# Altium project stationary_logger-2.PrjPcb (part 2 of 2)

## Sheet MCU_Power.SchDoc: Insert Title
size B; DrawnBy: Insert Name; Organization: NH-GG; DocumentNumber: 12345; Revision: 1; SheetNumber: 5; SheetTotal: 11; nhSheetName: MCU Power
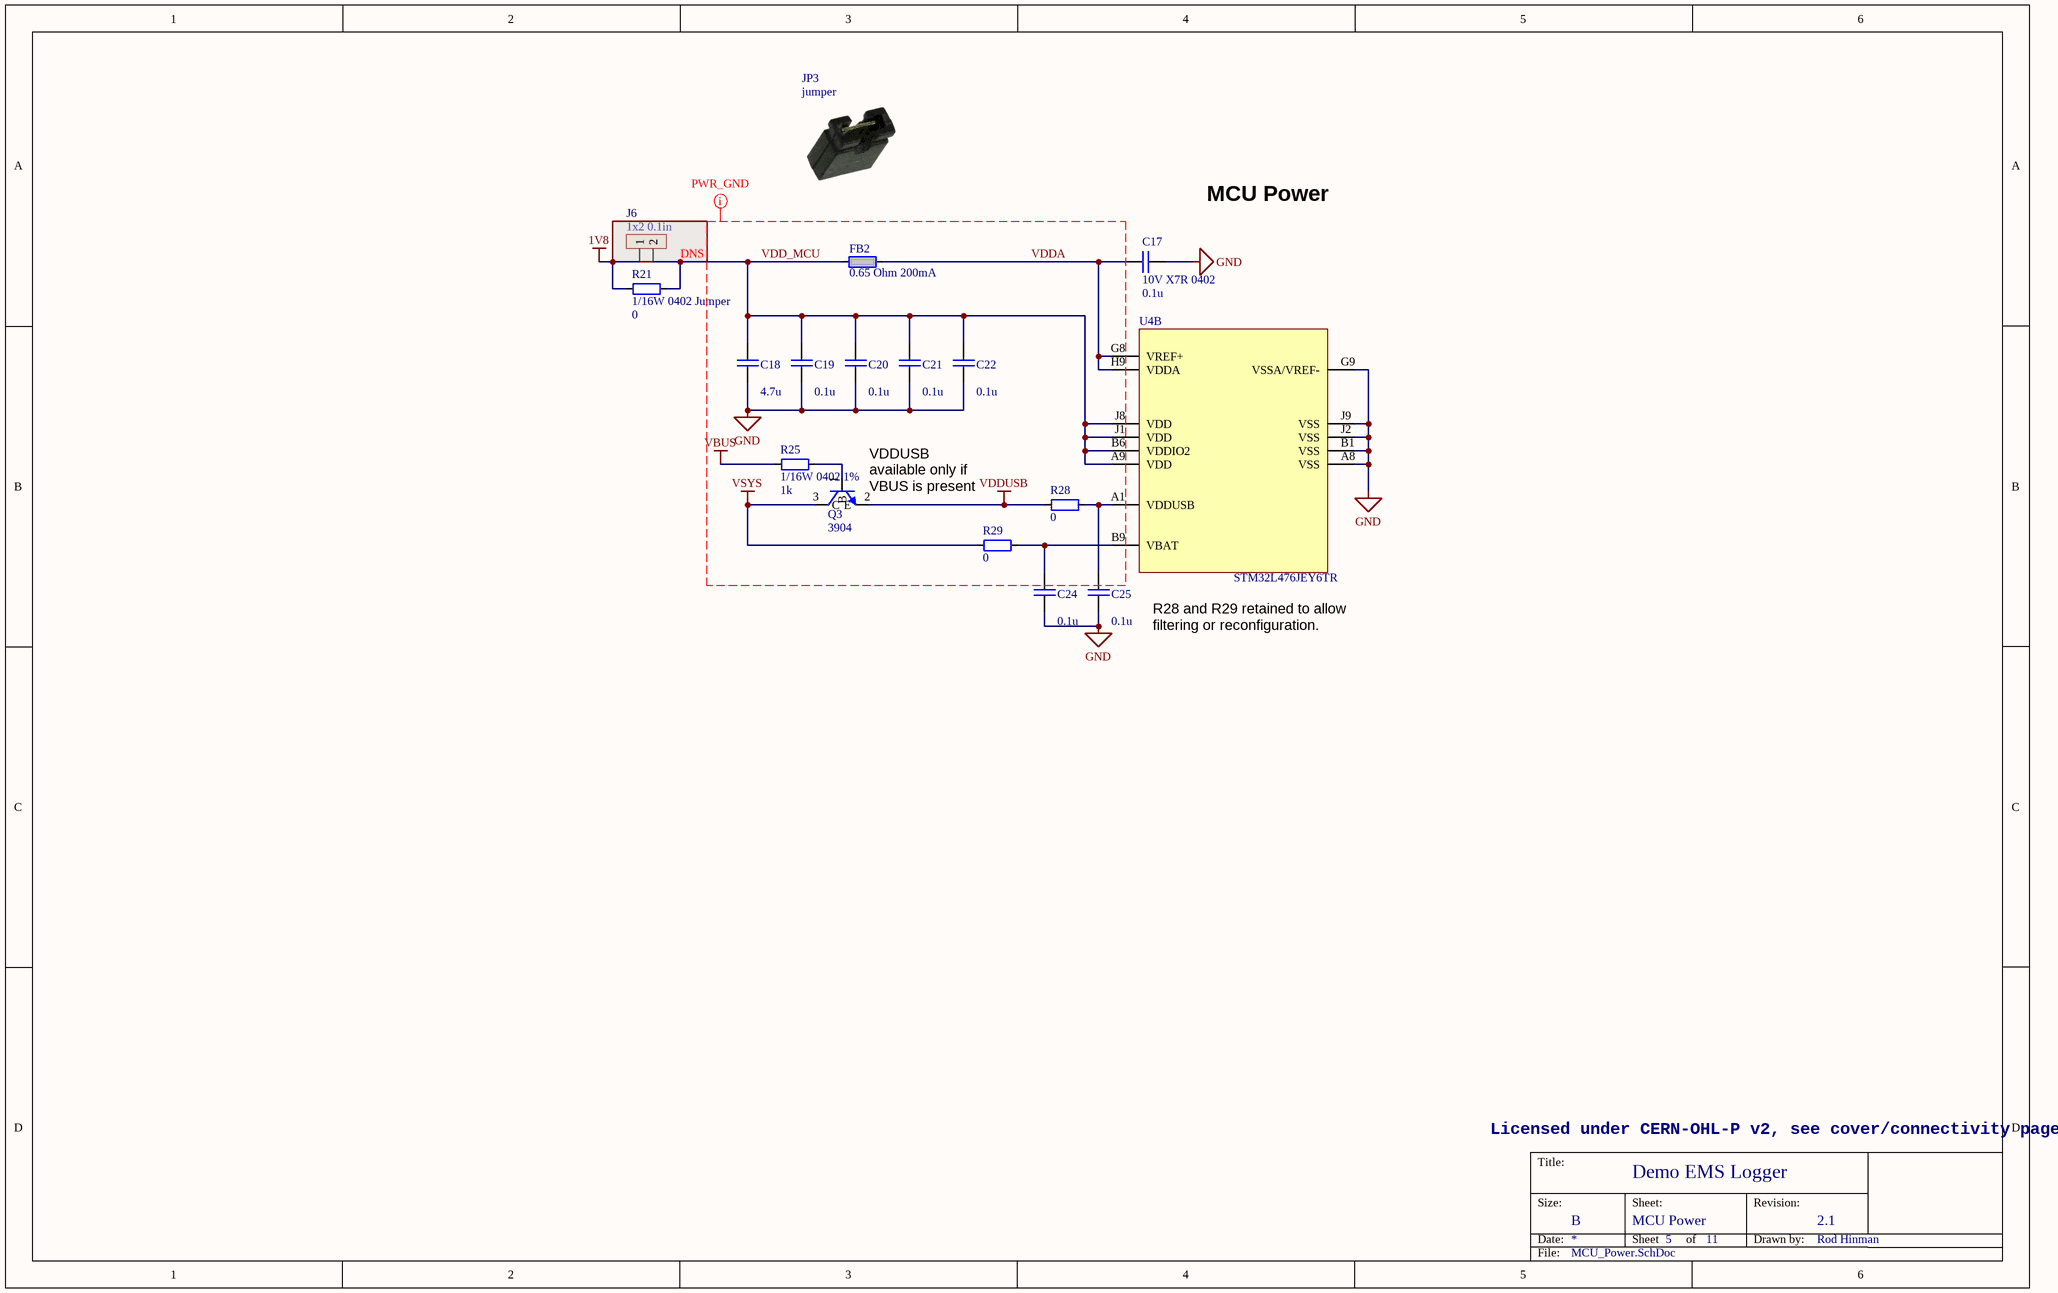
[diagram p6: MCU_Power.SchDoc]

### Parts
C17  10V X7R 0402  value_text: 0.1u  [CAPC1005X55,0402,L]
C18  value_text: 4.7u  [CAPC1608X100,0603,L]  (hidden comment: 16V X7R 0603)
C19  value_text: 0.1u  [CAPC1005X55,0402,L]  (hidden comment: 10V X7R 0402)
C20  value_text: 0.1u  [CAPC1005X55,0402,L]  (hidden comment: 10V X7R 0402)
C21  value_text: 0.1u  [CAPC1005X55,0402,L]  (hidden comment: 10V X7R 0402)
C22  value_text: 0.1u  [CAPC1005X55,0402,L]  (hidden comment: 10V X7R 0402)
C24  value_text: 0.1u  [CAPC1005X55,0402,L]  (hidden comment: 10V X7R 0402)
C25  value_text: 0.1u  [CAPC1005X55,0402,L]  (hidden comment: 10V X7R 0402)
FB2  0.65 Ohm 200mA  [FER1005X60,0402,L]
J6  1x2 0.1in  [HDR_2PIN]
JP3  jumper  [SULLINS_QPC02SXGN-RC]
Q3  3904  [SOT23-3]
R21  1/16W 0402 Jumper  value_text: 0  [RESC1005X40,0402,L]
R25  1/16W 0402 1%  value_text: 1k  [RESC1005X40,0402,L]
R28  value_text: 0  [RESC1005X40,0402,L]  (hidden comment: 1/16W 0402 Jumper)
R29  value_text: 0  [RESC1005X40,0402,L]  (hidden comment: 1/16W 0402 Jumper)
U4  STM32L476JEY6TR  [STM_BGA72C40P9X9_441X376X58]  (part B of 2)

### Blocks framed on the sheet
DNS: J6

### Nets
1V8: J6.1 R21.1
GND: C17.2 C18.1 C19.1 C20.1 C21.1 C22.1 C24.1 C25.1 U4.A8(VSS) U4.B1(VSS) U4.G9(VSSA/VREF-) U4.J2(VSS) U4.J9(VSS)
VBUS: R25.1
VDDUSB: Q3.2(E) R28.2
VSYS: Q3.3(C) R29.2
VDD_MCU: C18.2 C19.2 C20.2 C21.2 C22.2 FB2.1 J6.2 R21.2 U4.A9(VDD) U4.B6(VDDIO2) U4.J1(VDD) U4.J8(VDD)
VDDA: C17.1 FB2.2 U4.G8(VREF+) U4.H9(VDDA)
NetC24_2: C24.2 R29.1 U4.B9(VBAT)
NetC25_2: C25.2 R28.1 U4.A1(VDDUSB)
NetQ3_1: Q3.1(B) R25.2

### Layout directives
net class PWR_GND: GND, VBUS, VDD_MCU, VDDA, VDDUSB, VSYS

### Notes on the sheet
- MCU Power
- (near Q3) VDDUSB available only if VBUS is present
- R28 and R29 retained to allow filtering or reconfiguration.
- Licensed under CERN-OHL-P v2, see cover/connectivity page.

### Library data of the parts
C17 C19-C22 C24 C25 = CAP-00140: 0.1µF ±10% 10V Ceramic Capacitor X7R 0402 (1005 Metric); manufacturer_pn: CL05B104KP5NNNC; manufacturer: Samsung Electro-Mechanics America, Inc.; id: 479140; value: 1E-7
C18 = CAP-00136: CAP CER 4.7UF 16V X5R 0603; manufacturer_pn: CL10A475KO8NNNC; manufacturer: Samsung Electro-Mechanics America, Inc.; id: 468089; value: 4.7E-6
FB2 = FER-00014: FERRITE BEAD 600 OHM 0402 1LN; manufacturer_pn: BLM15BD601SN1D; manufacturer: Murata Electronics North America; id: 468096; value_text: 600; value: 600
J6 = CONN-00001: 2 Positions Header, Unshrouded Connector 0.100" (2.54mm) Through Hole Gold; manufacturer_pn: 961102-6404-AR; manufacturer: 3M; id: 136490
JP3 = MECH-00014: 2 (1 x 2) Position Shunt Connector Black Open Top 0.100" (2.54mm) Gold; manufacturer_pn: QPC02SXGN-RC; manufacturer: Sullins Connector Solutions; id: 138116
Q3 = BJT-00000: TRANS NPN 40V 0.2A SOT23; manufacturer_pn: MMBT3904LT1G; manufacturer: ON Semiconductor; id: 138488
R21 R28 R29 = RES-00093: 0.0 Ohm Jumper 0.063W, 1/16W Chip Resistor 0402 (1005 Metric) Moisture Resistant Thick Film; manufacturer_pn: RC0402JR-070RL; manufacturer: Yageo; id: 168185; value: 0
R25 = RES-00090: 1k Ohm ±1% 0.063W, 1/16W Chip Resistor 0402 (1005 Metric) Moisture Resistant Thick Film; manufacturer_pn: RC0402FR-071KL; manufacturer: Yageo; id: 168133; value: 1000
U4 = MCU-00028: IC MCU 32BIT 512KB FLASH WLCSP72; manufacturer: STMicroelectronics; id: 474854

## Sheet USB.SchDoc: Insert Title
size B; DrawnBy: Insert Name; Organization: NH-GG; DocumentNumber: 12345; Revision: 1; SheetNumber: 9; SheetTotal: 11; nhSheetName: USB
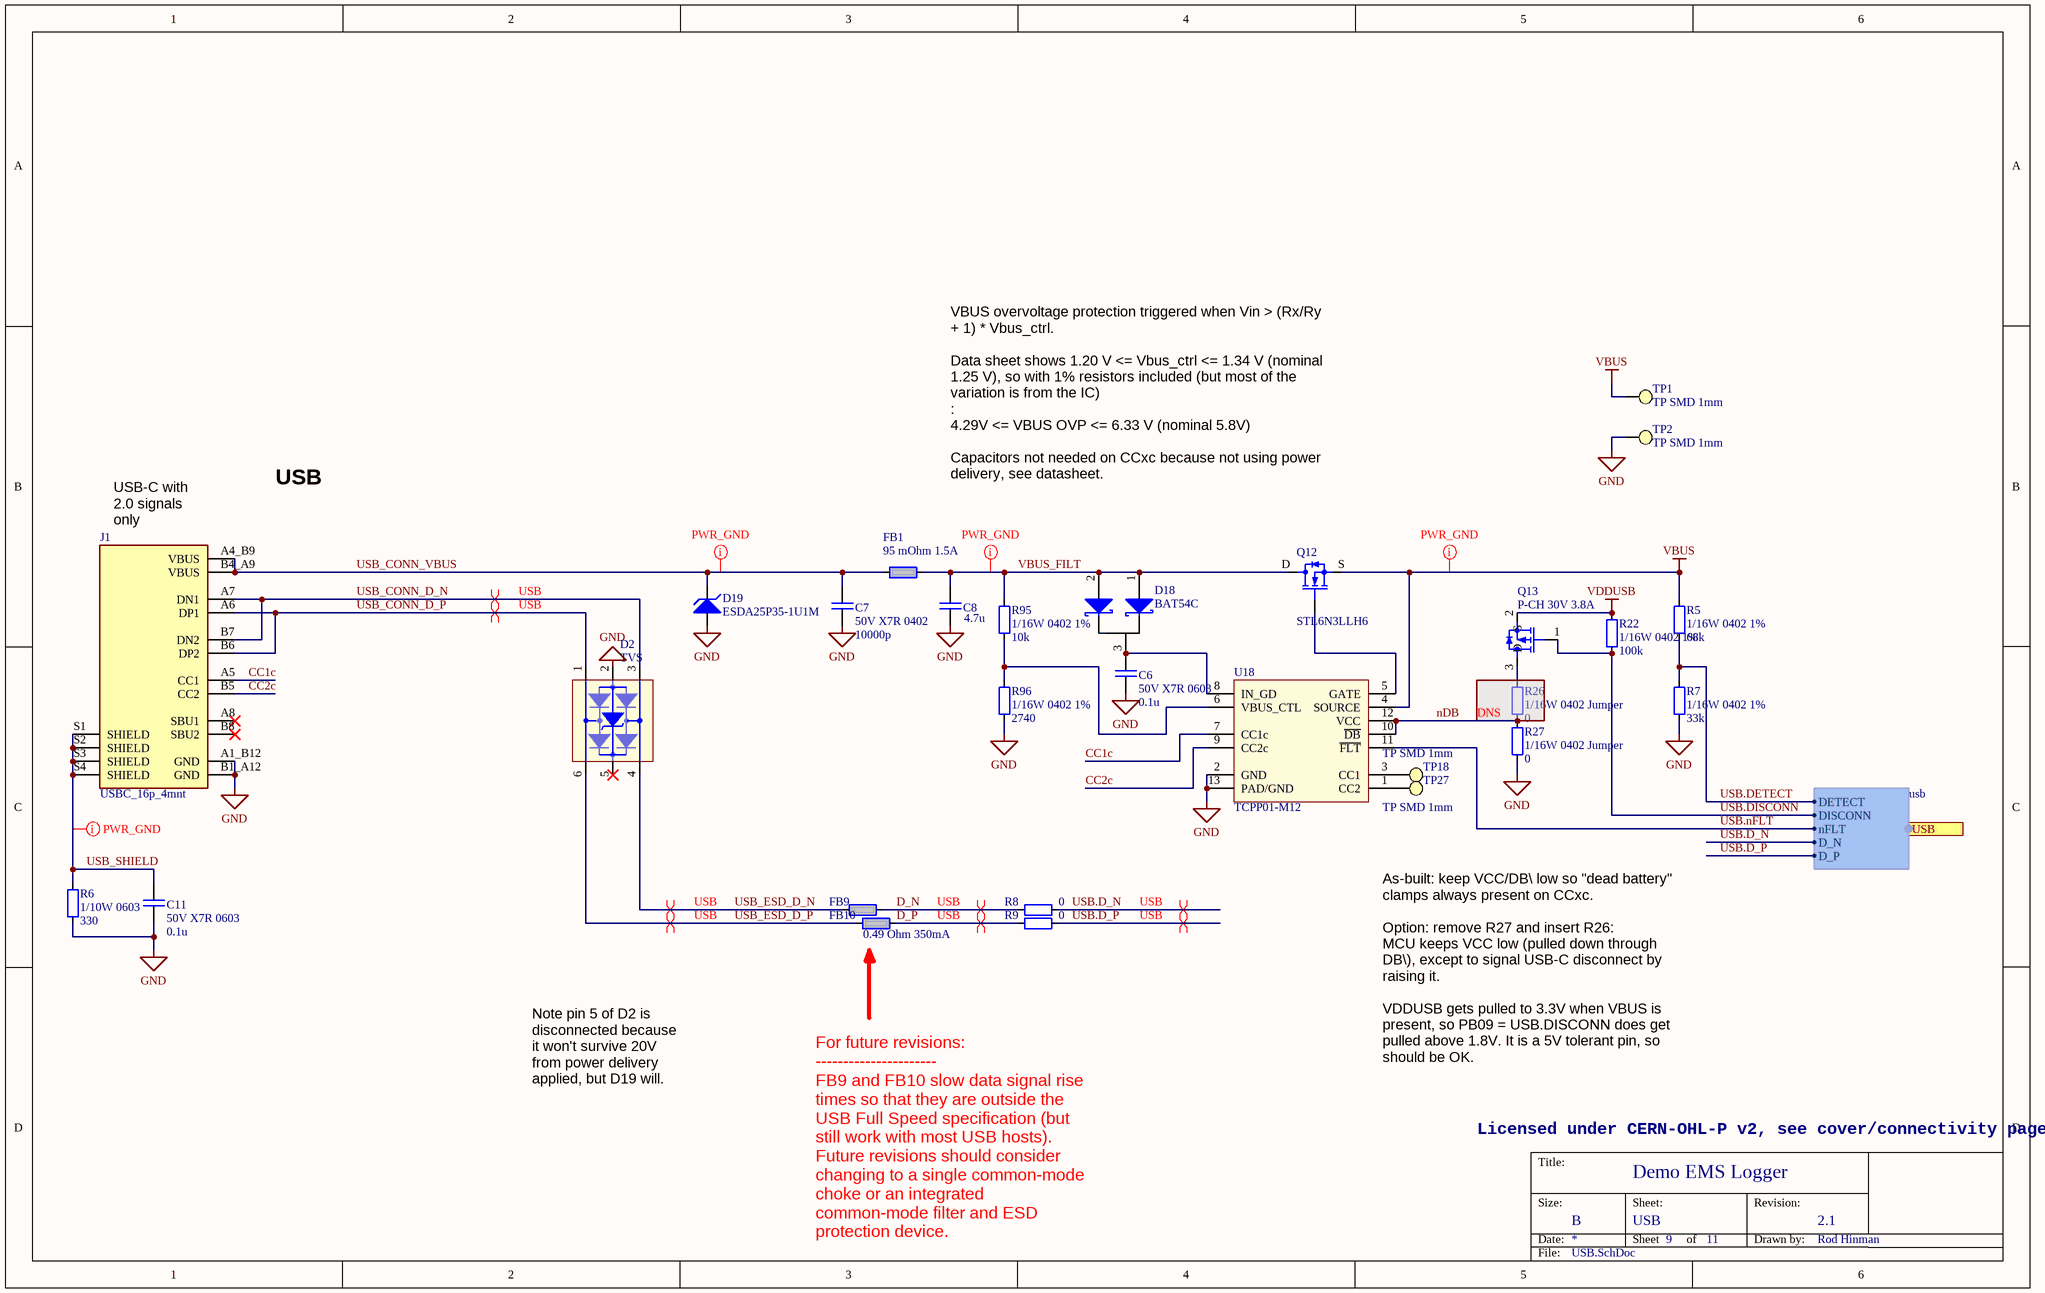
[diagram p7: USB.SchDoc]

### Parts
C6  50V X7R 0603  value_text: 0.1u  [CAPC1608X100,0603,L]
C7  50V X7R 0402  value_text: 10000p  [CAPC1005X60,0402,L]
C8  value_text: 4.7u  [CAPC1608X100,0603,L]  (hidden comment: 16V X7R 0603)
C11  50V X7R 0603  value_text: 0.1u  [CAPC1608X100,0603,L]
D2  TVS  [SOT23-6]
D18  BAT54C  [SOT23-3B]
D19  manufacturer_pn: ESDA25P35-1U1M  [DFN105P160X60-2N]  (hidden comment: 22WVM)
FB1  95 mOhm 1.5A  [FER1005X60,0402,L]
FB9  0.49 Ohm 350mA  [FER1005X60,0402,L]  (value not drawn)
FB10  0.49 Ohm 350mA  [FER1005X60,0402,L]
J1  USBC_16p_4mnt  [GCT_USB4105]
Q12  manufacturer_pn: STL6N3LLH6  [STM_PWRFLAT_SON65P200X80_HS-8N]  (hidden comment: N-CH 30V)
Q13  P-CH 30V 3.8A  [SOT23-3]
R5  1/16W 0402 1%  value_text: 68k  [RESC1005X40,0402,L]
R6  1/10W 0603  value_text: 330  [RESC1608X60,0603,L]
R7  1/16W 0402 1%  value_text: 33k  [RESC1005X40,0402,L]
R8  value_text: 0  [RESC1005X40,0402,L]  (hidden comment: 1/16W 0402 Jumper)
R9  value_text: 0  [RESC1005X40,0402,L]  (hidden comment: 1/16W 0402 Jumper)
R22  1/16W 0402 1%  value_text: 100k  [RESC1005X40,0402,L]
R26  1/16W 0402 Jumper  value_text: 0  [RESC1005X40,0402,L]
R27  1/16W 0402 Jumper  value_text: 0  [RESC1005X40,0402,L]
R95  1/16W 0402 1%  value_text: 10k  [RESC1005X40,0402,L]
R96  1/16W 0402 1%  value_text: 2740  [RESC1005X40,0402,L]
TP1  TP SMD 1mm  [TP_SMD_Ø1.0mm NO SILK]  (no BOM)
TP2  TP SMD 1mm  [TP_SMD_Ø1.0mm NO SILK]  (no BOM)
TP18  TP SMD 1mm  [TP_SMD_Ø1.0mm NO SILK]  (no BOM)
TP27  TP SMD 1mm  [TP_SMD_Ø1.0mm NO SILK]  (no BOM)
U18  manufacturer_pn: TCPP01-M12  [QFN50P300X300X100_HS-13N]  (hidden comment: STM_TCPP01-M12)

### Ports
USB (out, harness usb)

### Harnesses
usb: DETECT, DISCONN, D_N, D_P, nFLT

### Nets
GND: C6.2 C7.1 C8.1 C11.2 D2.2(GND) D19.A J1.A1_B12(GND) J1.B1_A12(GND) R6.2 R7.1 R27.1 R96.1 TP2.1 U18.2(GND) U18.13(PAD/GND)
VBUS: Q12.S R5.2 TP1.1 U18.4(SOURCE)
VDDUSB: Q13.2(S) R22.1
CC1c: J1.A5(CC1) U18.7(CC1c)
CC2c: J1.B5(CC2) U18.9(CC2c)
D_N: FB9.2 R8.2
D_P: FB10.2 R9.2
nDB: R26.1 R27.2 U18.10(~{DB}) U18.12(VCC)
USB.D_N: R8.1 ; port USB.D_N
USB.D_P: R9.1 ; port USB.D_P
USB.DETECT: R5.1 R7.2 ; port USB.DETECT
USB.DISCONN: Q13.1(G) R22.2 ; port USB.DISCONN
USB.nFLT: U18.11(~{FLT}) ; port USB.nFLT
USB_CONN_D_N: D2.3(D-IN) J1.A7(DN1) J1.B7(DN2)
USB_CONN_D_P: D2.1(D+IN) J1.A6(DP1) J1.B6(DP2)
USB_CONN_VBUS: C7.2 D19.K FB1.1 J1.A4_B9(VBUS) J1.B4_A9(VBUS)
USB_ESD_D_N: D2.4(D-OUT) FB9.1
USB_ESD_D_P: D2.6(D+OUT) FB10.1
USB_SHIELD: C11.1 J1.S1(SHIELD) J1.S2(SHIELD) J1.S3(SHIELD) J1.S4(SHIELD) R6.1
VBUS_FILT: C8.2 D18.1 D18.2 FB1.2 Q12.D R95.2
NetC6_1: C6.1 D18.3 U18.8(IN_GD)
NetQ12_G: Q12.G U18.5(GATE)
NetQ13_3: Q13.3(D) R26.2
NetR95_1: R95.1 R96.2 U18.6(VBUS_CTL)
NetTP18_1: TP18.1 U18.3(CC1)
NetTP27_1: TP27.1 U18.1(CC2)

Not connected (* = marked no-connect by the designer): D2 5(VBUS)*; J1 A8(SBU1)* B8(SBU2)*

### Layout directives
net class PWR_GND: USB_CONN_VBUS, USB_SHIELD, VBUS, VBUS_FILT
differential pair; differential pair class USB; net class USB: D_N, D_P, USB.D_N, USB.D_P, USB_CONN_D_N, USB_CONN_D_P, USB_ESD_D_N, USB_ESD_D_P

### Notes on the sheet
- USB
- VBUS overvoltage protection triggered when Vin > (Rx/Ry + 1) * Vbus_ctrl.
  Data sheet shows 1.20 V <= Vbus_ctrl <= 1.34 V (nominal 1.25 V), so with 1% resistors included (but most of the variation is from the IC)
  :
  4.29V <= VBUS OVP <= 6.33 V (nominal 5.8V)
  Capacitors not needed on CCxc because not using power delivery, see datasheet.
- (near J1) USB-C with 2.0 signals only
- DNS
- As-built: keep VCC/DB\ low so "dead battery" clamps always present on CCxc.
  Option: remove R27 and insert R26:
  MCU keeps VCC low (pulled down through DB\), except to signal USB-C disconnect by raising it.
  VDDUSB gets pulled to 3.3V when VBUS is present, so PB09 = USB.DISCONN does get pulled above 1.8V. It is a 5V tolerant pin, so should be OK.
- Note pin 5 of D2 is disconnected because it won't survive 20V from power delivery applied, but D19 will.
- Licensed under CERN-OHL-P v2, see cover/connectivity page.
- For future revisions:
  ----------------------
  FB9 and FB10 slow data signal rise times so that they are outside the USB Full Speed specification (but still work with most USB hosts).  Future revisions should consider changing to a single common-mode choke or an integrated common-mode filter and ESD protection device.

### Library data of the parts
C6 C11 = CAP-00138: CAP CER 0.1UF 50V X7R 0603; manufacturer_pn: CL10B104KB8NNNC; manufacturer: Samsung Electro-Mechanics America, Inc.; id: 468091; value: 1E-7
C7 = CAP-00114: 10000pF ±10% 50V Ceramic Capacitor X7R 0402 (1005 Metric); manufacturer_pn: C0402C103K5RAC7867; manufacturer: Kemet; id: 288967; value: 1E-8
C8 = CAP-00136: as C18 on sheet MCU_Power
D2 = DIO-00054: TVS DIODE 5.25VWM 17VC SOT23-6; manufacturer_pn: USBLC6-2SC6; manufacturer: STMicroelectronics; id: 468100
D18 = DIO-00052: Diode Array 1 Pair Common Cathode Schottky 30 V 200mA (DC) Surface Mount TO-236-3, SC-59, SOT-23-3; manufacturer_pn: BAT54C,215; manufacturer: Nexperia USA Inc.; id: 460427
D19 = DIO-00057: TVS DIODE 22VWM 31VC; manufacturer: STMicroelectronics; id: 475009
FB1 = FER-00015: FERRITE BEAD 220 OHM 0402 1LN; manufacturer_pn: MPZ1005S221HT000; manufacturer: TDK Corporation; id: 468097; value_text: 220; value: 220
FB9 FB10 = FER-00013: FERRITE BEAD 1 KOHM 0402 1LN; manufacturer_pn: BLM15AX102SN1D; manufacturer: Murata Electronics North America; id: 468095; value_text: 1k; value: 1000
J1 = CONN-00185: CONN RCP USB2.0 TYP C 24P SMD RA; manufacturer: GCT; manufacturer_pn: USB4105-GF-A; id: 477100; MF: CUI Devices; MP: UJ31-CH-3-MSMT-TR-67
Q12 = FET-00031: MOSFET N-Ch 30 V 0.021 Ohm 6 A; manufacturer: STMicroelectronics; id: 475008
Q13 = FET-00028: MOSFET P-CH 30V 3.8A SOT23; manufacturer_pn: DMP3099L-7; manufacturer: Diodes Incorporated; id: 468113
R5 = RES-00197: RES 68K OHM 1% 1/16W 0402; manufacturer_pn: RC0402FR-0768KL; manufacturer: Yageo; id: 468078; value: 68000
R6 = RES-00202: RES SMD 330 OHM 1% 1/10W 0603; manufacturer_pn: ERJ-3EKF3300V; manufacturer: Panasonic Electronic Components; id: 468084; value: 330
R7 = RES-00198: RES 33K OHM 1% 1/16W 0402; manufacturer_pn: RC0402FR-0733KL; manufacturer: Yageo; id: 468079; value: 33000
R8 R9 R26 R27 = RES-00093: as R21 on sheet MCU_Power
R22 = RES-00095: 100k Ohm ±1% 0.063W, 1/16W Chip Resistor 0402 (1005 Metric) Moisture Resistant Thick Film; manufacturer_pn: RC0402FR-07100KL; manufacturer: Yageo; id: 168197; value: 100000
R95 = RES-00094: 10k Ohm ±1% 0.063W, 1/16W Chip Resistor 0402 (1005 Metric) Moisture Resistant Thick Film; manufacturer_pn: RC0402FR-0710KL; manufacturer: Yageo; id: 168195; value: 10000
R96 = RES-00205: RES 2.74K OHM 1% 1/16W 0402; manufacturer_pn: RC0402FR-072K74L; manufacturer: Yageo; id: 475656; value: 2740
TP1 TP2 TP18 TP27 = NOBOM-00001: Test point, SMD, 1mm dia (0.040"); manufacturer: New Horizons; id: 137197
U18 = ICXCV-00034: USB-C interface IC Overvoltage Protection; manufacturer: STMicroelectronics; id: 474978

## Sheet XX-Changelog.SchDoc: Insert Title
size B; DrawnBy: Insert Name; Organization: NH-GG; DocumentNumber: 12345; Revision: 1; SheetNumber: 11; SheetTotal: 11; nhSheetName: Change Log
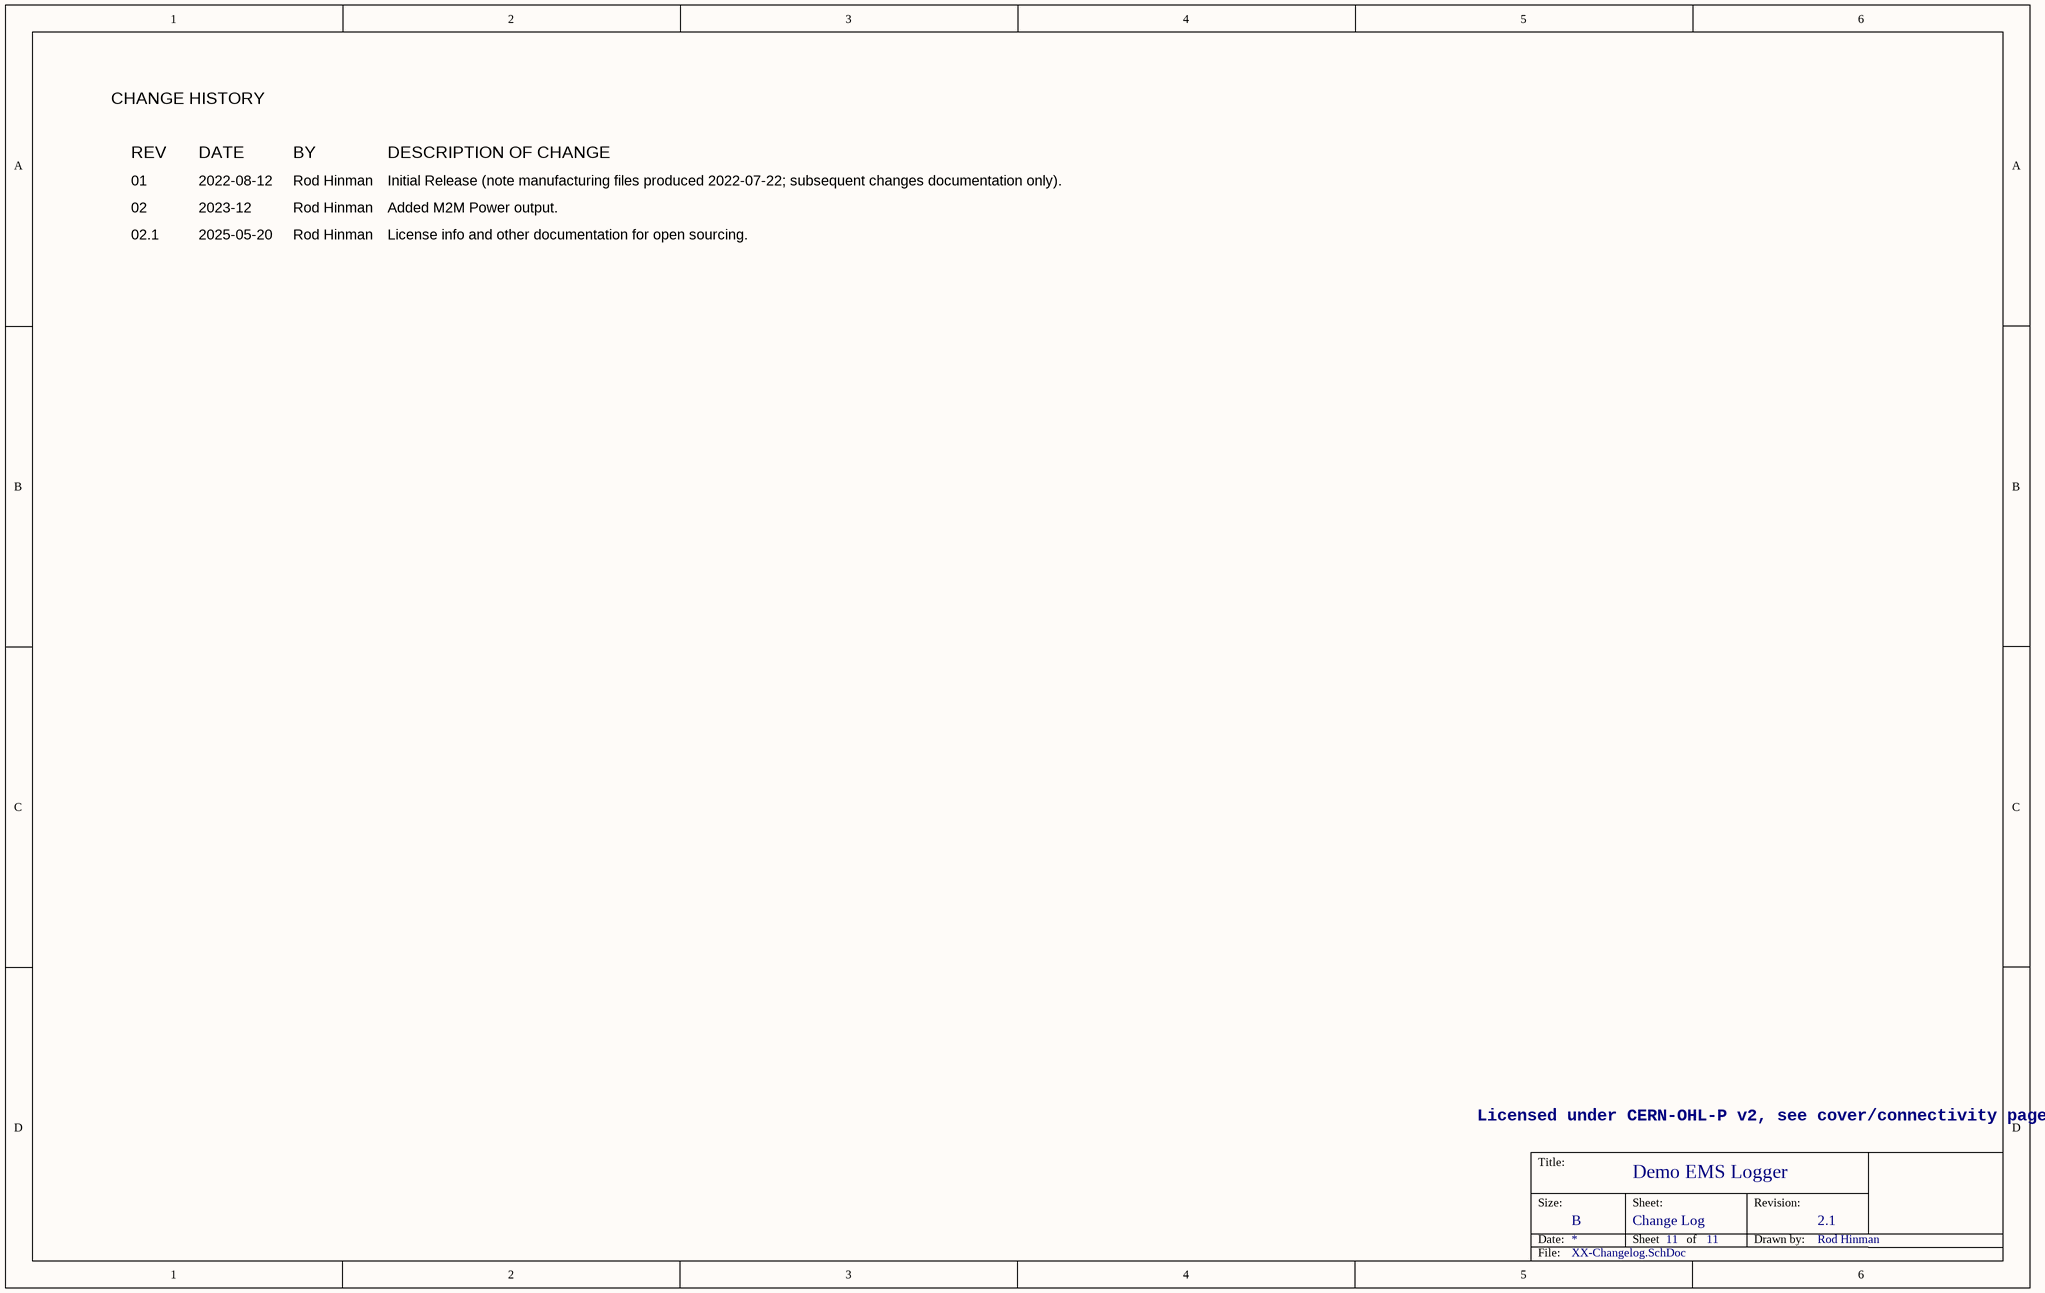
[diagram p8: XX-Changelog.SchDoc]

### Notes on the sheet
- CHANGE HISTORY
- REV
- DATE
- BY
- DESCRIPTION OF CHANGE
- 01
- 02
- 2022-08-12
- 2023-12
- Rod Hinman
- Initial Release (note manufacturing files produced 2022-07-22; subsequent changes documentation only).
- Added M2M Power output.
- 02.1
- 2025-05-20
- License info and other documentation for open sourcing.
- Licensed under CERN-OHL-P v2, see cover/connectivity page.

## Sheet Overview.SchDoc
size B; DrawnBy: Insert Name; Organization: NH-GG; DocumentNumber: 12345; Revision: 1; SheetNumber: 2; SheetTotal: 11; nhSheetName: Overview / General Info
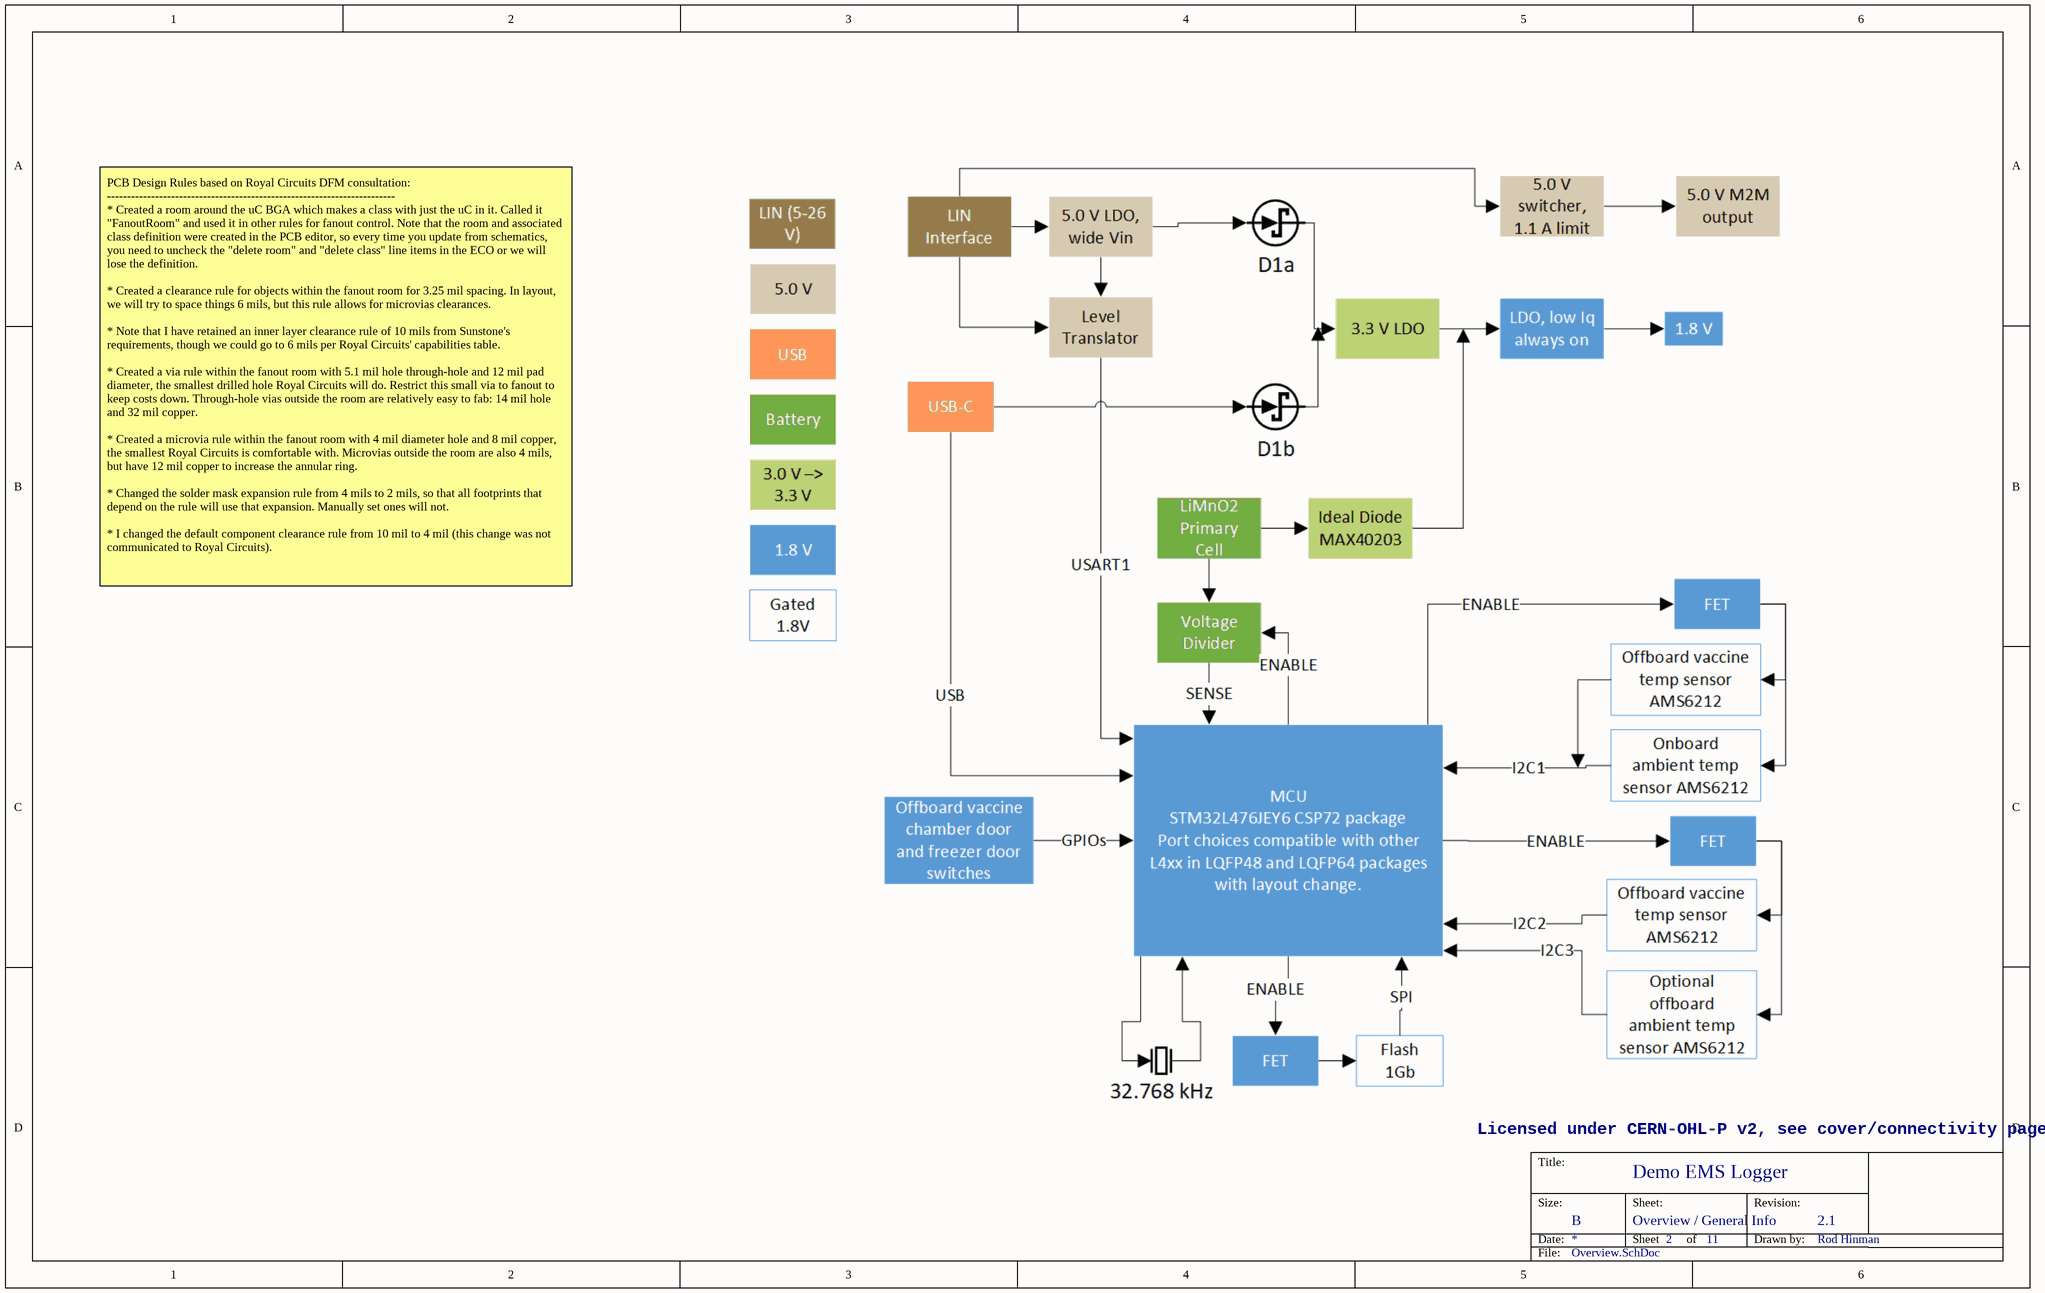
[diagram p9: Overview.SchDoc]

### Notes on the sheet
- PCB Design Rules based on Royal Circuits DFM consultation:
  ------------------------------------------------------------------------
  * Created a room around the uC BGA which makes a class with just the uC in it. Called it "FanoutRoom" and used it in other rules for fanout control. Note that the room and associated class definition were created in the PCB editor, so every time you update from schematics, you need to uncheck the "delete room" and "delete class" line items in the ECO or we will lose the definition.
  * Created a clearance rule for objects within the fanout room for 3.25 mil spacing. In layout, we will try to space things 6 mils, but this rule allows for microvias clearances.
  * Note that I have retained an inner layer clearance rule of 10 mils from Sunstone's requirements, though we could go to 6 mils per Royal Circuits' capabilities table.
  * Created a via rule within the fanout room with 5.1 mil hole through-hole and 12 mil pad diameter, the smallest drilled hole Royal Circuits will do. Restrict this small via to fanout to keep costs down. Through-hole vias outside the room are relatively easy to fab: 14 mil hole and 32 mil copper.
  * Created a microvia rule within the fanout room with 4 mil diameter hole and 8 mil copper, the smallest Royal Circuits is comfortable with. Microvias outside the room are also 4 mils, but have 12 mil copper to increase the annular ring.
  * Changed the solder mask expansion rule from 4 mils to 2 mils, so that all footprints that depend on the rule will use that expansion. Manually set ones will not.
  * I changed the default component clearance rule from 10 mil to 4 mil (this change was not communicated to Royal Circuits).
- Licensed under CERN-OHL-P v2, see cover/connectivity page.

## Sheet M2M_Power.SchDoc: Insert Title
size B; DrawnBy: Insert Name; Organization: NH-GG; DocumentNumber: 12345; Revision: 1; SheetNumber: 10; SheetTotal: 11; nhSheetName: M2M Power
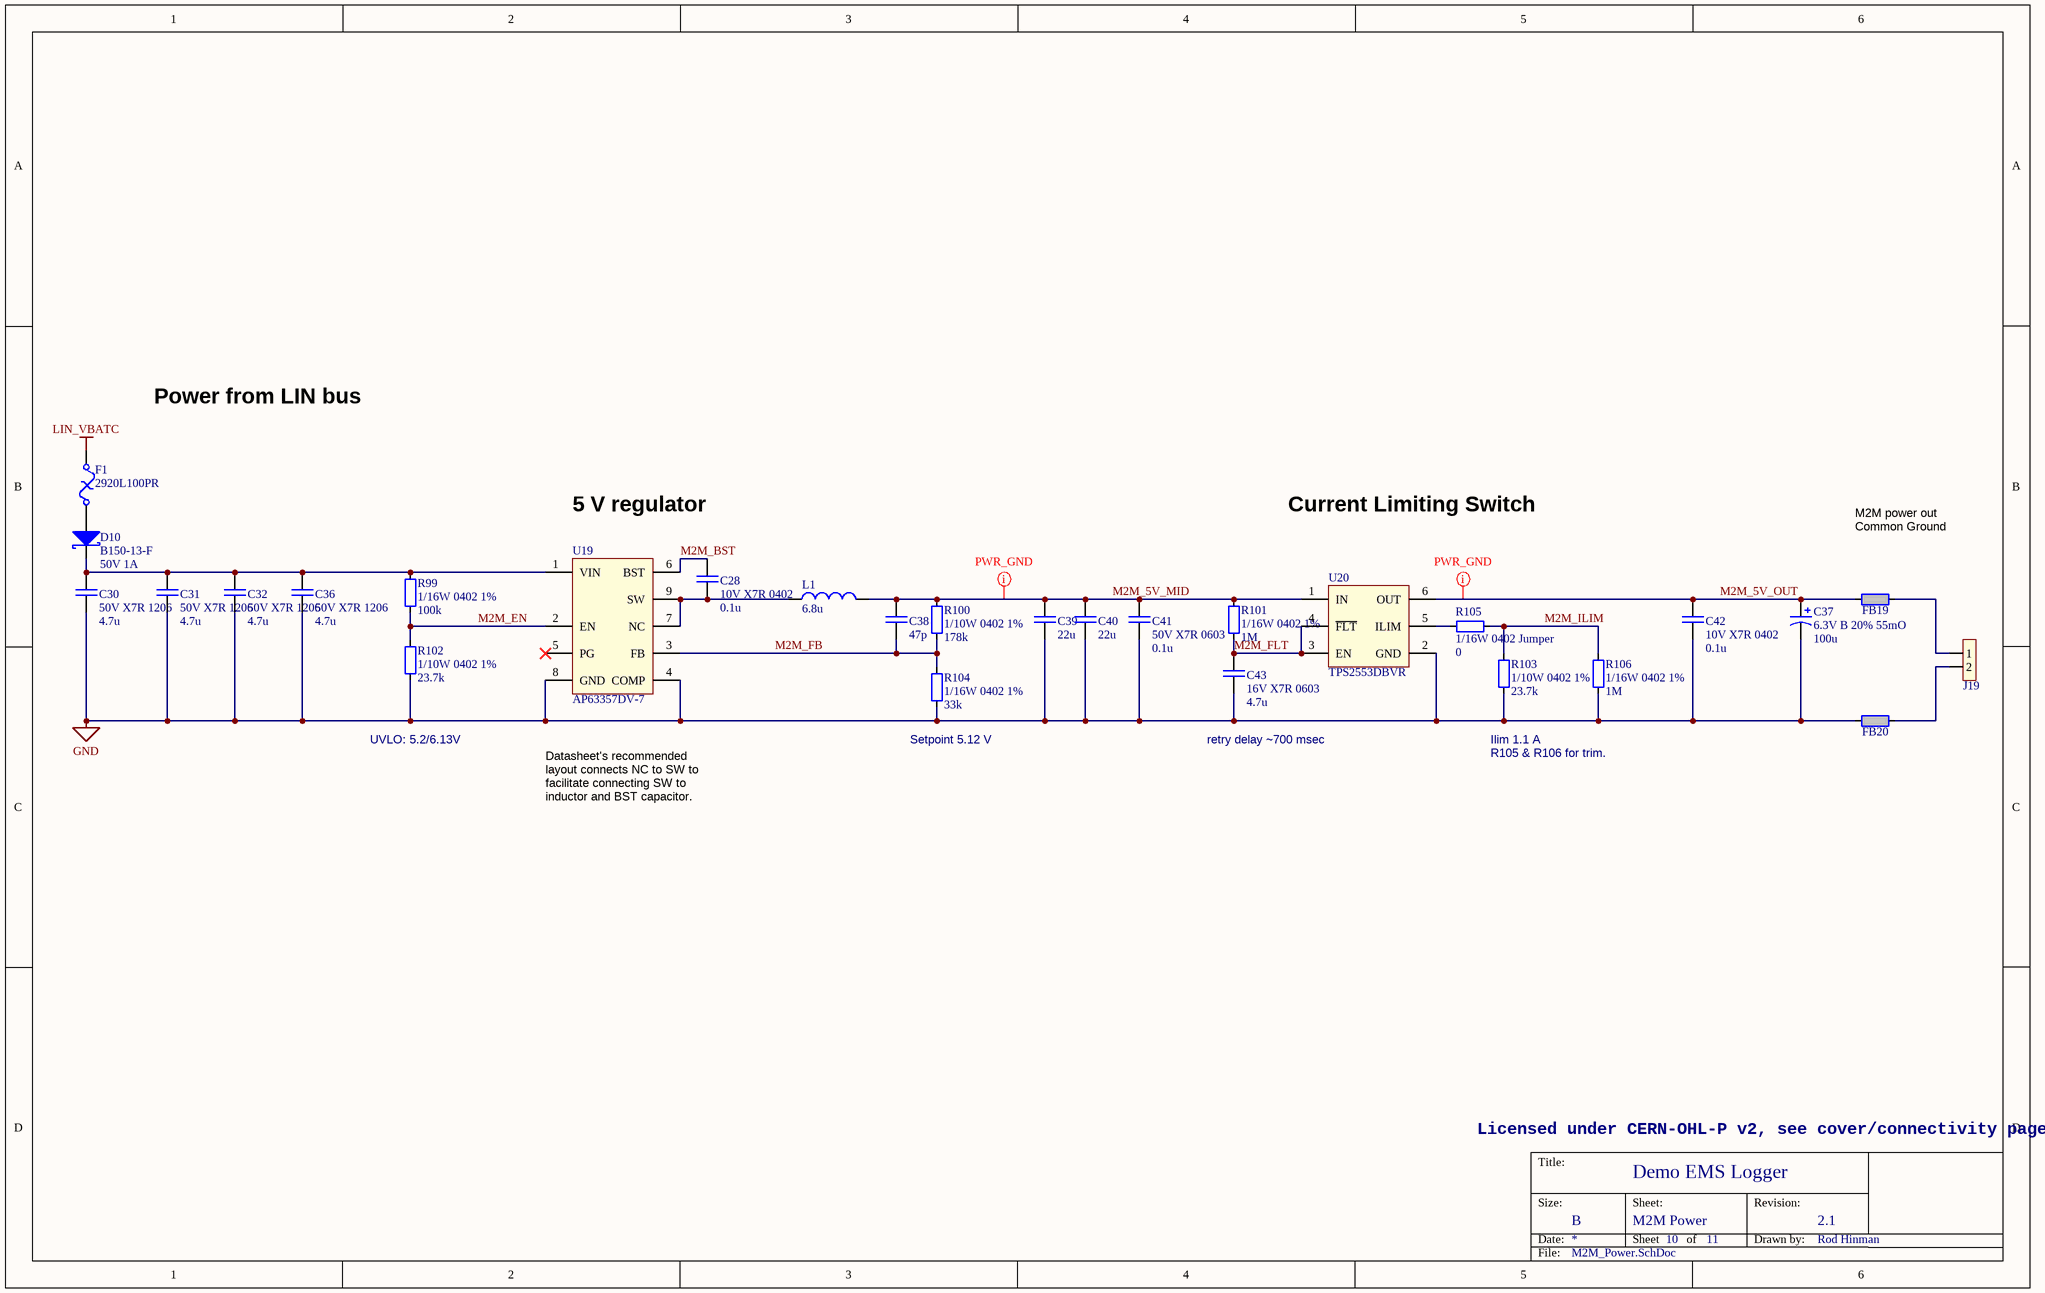
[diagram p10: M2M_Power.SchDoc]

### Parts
C28  10V X7R 0402  value_text: 0.1u  [CAPC1005X55,0402,L]
C30  50V X7R 1206  value_text: 4.7u  [CAPC3216X190,1206,L]
C31  50V X7R 1206  value_text: 4.7u  [CAPC3216X190,1206,L]
C32  50V X7R 1206  value_text: 4.7u  [CAPC3216X190,1206,L]
C36  50V X7R 1206  value_text: 4.7u  [CAPC3216X190,1206,L]
C37  6.3V B 20% 55mO  value_text: 100u  [CAPMP3528X21N[SIZEB]]
C38  value_text: 47p  [CAPC1005X55,0402,L]  (hidden comment: 50V C0G 0402)
C39  value_text: 22u  [CAPC2012X145]  (hidden comment: 16V X5R 0805)
C40  value_text: 22u  [CAPC2012X145]  (hidden comment: 16V X5R 0805)
C41  50V X7R 0603  value_text: 0.1u  [CAPC1608X100,0603,L]
C42  10V X7R 0402  value_text: 0.1u  [CAPC1005X55,0402,L]
C43  16V X7R 0603  value_text: 4.7u  [CAPC1608X100,0603,L]
D10  50V 1A  manufacturer_pn: B150-13-F  [DO-214AC_DIODES]
F1  manufacturer_pn: 2920L100PR  [FUSC7351X12N,2920,]  (hidden comment: 33V 1.1A)
FB19  220 Ohm 2A  [FER1608X100,0603,L]  (value not drawn)
FB20  220 Ohm 2A  [FER1608X100,0603,L]  (value not drawn)
J19  JST XH  [JST_S2B-XH-A(LF)(SN)_LESS_SILK]  (value not drawn)
L1  value_text: 6.8u  [INDUCTOR-BOURNS_SRN6045]  (hidden comment: 3A 31mOhm)
R99  1/16W 0402 1%  value_text: 100k  [RESC1005X40,0402,L]
R100  1/10W 0402 1%  value_text: 178k  [RESC1005X40,0402,L]
R101  1/16W 0402 1%  value_text: 1M  [RESC1005X40,0402,L]
R102  1/10W 0402 1%  value_text: 23.7k  [RESC1005X40,0402,L]
R103  1/10W 0402 1%  value_text: 23.7k  [RESC1005X40,0402,L]
R104  1/16W 0402 1%  value_text: 33k  [RESC1005X40,0402,L]
R105  1/16W 0402 Jumper  value_text: 0  [RESC1005X40,0402,L]
R106  1/16W 0402 1%  value_text: 1M  [RESC1005X40,0402,L]
U19  manufacturer_pn: AP63357DV-7  [DIO_VDFN3020-13A]  (hidden comment: DIO-AP6335x)
U20  manufacturer_pn: TPS2553DBVR  [SOT_23_6]  (hidden comment: TI_TPS2553)

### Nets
GND: C30.1 C31.1 C32.1 C36.1 C37.- C39.2 C40.2 C41.1 C42.1 C43.1 FB20.1 R102.2 R103.2 R104.2 R106.2 U19.4(COMP) U19.8(GND) U20.2(GND)
LIN_VBATC: F1.2
M2M_5V_MID: C38.1 C39.1 C40.1 C41.2 L1.2 R100.1 R101.1 U20.1(IN)
M2M_5V_OUT: C37.+ C42.2 FB19.1 U20.6(OUT)
M2M_BST: C28.2 U19.6(BST)
M2M_EN: R99.2 R102.1 U19.2(EN)
M2M_FB: C38.2 R100.2 R104.1 U19.3(FB)
M2M_FLT: C43.2 R101.2 U20.3(EN) U20.4(~{FLT})
M2M_ILIM: R103.1 R105.2 R106.1
NetC28_1: C28.1 L1.1 U19.7(NC) U19.9(SW)
NetC30_2: C30.2 C31.2 C32.2 C36.2 D10.K R99.1 U19.1(VIN)
NetD10_A: D10.A F1.1
NetFB19_2: FB19.2 J19.1
NetFB20_2: FB20.2 J19.2
NetR105_1: R105.1 U20.5(ILIM)

Not connected (* = marked no-connect by the designer): U19 5(PG)*

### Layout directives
net class PWR_GND: M2M_5V_MID, M2M_5V_OUT

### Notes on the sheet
- Power from LIN bus
- 5 V regulator
- Current Limiting Switch
- (near FB19) M2M power out
  Common Ground
- UVLO: 5.2/6.13V
- (near R104) Setpoint 5.12 V
- retry delay ~700 msec
- Ilim 1.1 A
- R105 & R106 for trim.
- Datasheet's recommended layout connects NC to SW to facilitate connecting SW to inductor and BST capacitor.
- Licensed under CERN-OHL-P v2, see cover/connectivity page.

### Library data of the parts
C28 C42 = CAP-00140: as C17 on sheet MCU_Power
C30-C32 C36 = CAP-00142: 4.7 µF ±10% 50V Ceramic Capacitor X7R 1206 (3216 Metric); manufacturer_pn: C1206C475K5RAC7800; manufacturer: Kemet; id: 486592; value: 4.7E-6; reorder_quantity: 0
C37 = CAP-00029: 100µF Molded Tantalum - Polymer Capacitors 6.3V 1210 (3528 Metric) 55 mOhm 0.138" L x 0.110" W (3.50mm x 2.80mm); manufacturer_pn: TCJB107M006R0055; manufacturer: AVX Corporation; id: 137128; value: 0.0001; reorder_quantity: 0
C38 = CAP-00104: 47pF ±5% 50V Ceramic Capacitor C0G, NP0 0402 (1005 Metric); manufacturer: Wurth Electronics Inc; manufacturer_pn: 885012005059; id: 226042; reorder_quantity: 0; value: 4.7E-11
C39 C40 = CAP-00031: 22µF 16V Ceramic Capacitor X5R 0805 (2012 Metric) 0.079" L x 0.049" W (2.00mm x 1.25mm); manufacturer: Murata Electronics North America; manufacturer_pn: GRM21BR61C226ME44L; id: 137130; reorder_quantity: 0; value: 2.2E-5
C41 = CAP-00138: CAP CER 0.1UF 50V X7R 0603; manufacturer_pn: CL10B104KB8NNNC; manufacturer: Samsung Electro-Mechanics America, Inc.; id: 468091; value: 1E-7; reorder_quantity: 0
C43 = CAP-00136: CAP CER 4.7UF 16V X5R 0603; manufacturer_pn: CL10A475KO8NNNC; manufacturer: Samsung Electro-Mechanics America, Inc.; id: 468089; value: 4.7E-6; reorder_quantity: 0
D10 = DIO-00063: DIODE SCHOTTKY 50V 1A SMA; manufacturer: Diodes Incorporated; id: 520214; reorder_quantity: 0
F1 = FUSE-00012: Polymeric PTC Resettable Fuse 33V 1.1A Ih Surface Mount 2920 (7351 Metric), Concave; manufacturer: Littelfuse Inc.; id: 225978; reorder_quantity: 0
FB19 FB20 = FER-00004: FERRITE BEAD 220 OHM 0603 1LN 50m ohm; manufacturer_pn: BLM18EG221SN1D; manufacturer: Murata Electronics North America; value_text: 220; id: 137076; reorder_quantity: 0; value: 220
J19 = CONN-00192: CONN HEADER R/A 2POS 2.5MM; manufacturer_pn: S2B-XH-A(LF)(SN); manufacturer: JST Sales America Inc.; id: 516837; reorder_quantity: 0
L1 = IND-00035: FIXED IND 6.8UH 3A 31 MOHM SMD; manufacturer_pn: TYS60456R8M-10; manufacturer: Laird Technologies EMI; id: 516835; reorder_quantity: 0; value: 6.8E-6
R99 = RES-00095: as R22 on sheet USB
R100 = RES-00214: RES 178K OHM 1% 1/16W 0402; manufacturer_pn: RC0402FR-07178KL; manufacturer: Yageo; id: 516838; value: 178000; reorder_quantity: 0
R101 R106 = RES-00137: 1 MOhms ±1% 0.063W, 1/16W Chip Resistor 0402 (1005 Metric) Automotive AEC-Q200 Thick Film; manufacturer_pn: RC0402FR-071ML; manufacturer: Vishay Dale; id: 225970; value: 1000000; reorder_quantity: 0
R102 R103 = RES-00213: RES 23.7K OHM 1% 1/16W 0402; manufacturer_pn: RC0402FR-0723K7L; manufacturer: Yageo; id: 516836; value: 23700; reorder_quantity: 0
R104 = RES-00198: RES 33K OHM 1% 1/16W 0402; manufacturer_pn: RC0402FR-0733KL; manufacturer: Yageo; id: 468079; value: 33000; reorder_quantity: 0
R105 = RES-00093: as R21 on sheet MCU_Power
U19 = ICPWR-00067: IC REG BUCK ADJ 3.5A 13DFN; manufacturer: Diodes Incorporated; id: 516829; reorder_quantity: 0
U20 = ICPWR-00068: IC PWR SWITCH N-CHAN 1:1 SOT23-6; manufacturer: Texas Instruments; id: 516834; reorder_quantity: 0

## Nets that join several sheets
1V8: MCU (R34.1 S1.4), Power (J3.2 R13.2 TP5.1), LIN (R63.2 R69.1), Sensors (J9.1 J11.1 R45.1 R54.1), Flash (J15.1 R71.1), MCU_Power (J6.1 R21.1)
5V_LIN: Power (D1.2 D8.2), LIN (7 pins)
GND: MCU (21 pins), Power (26 pins), LIN (14 pins), Sensors (16 pins), Flash (C35.1 U12.4 U12.9), MCU_Power (13 pins), USB (15 pins), M2M_Power (18 pins)
LIN_VBATC: LIN (C1.1 D14.A FB6.1), M2M_Power (F1.2)
VBUS: Power (D1.1 D8.1), MCU_Power (R25.1), USB (Q12.S R5.2 TP1.1 U18.4)
VDDUSB: MCU_Power (Q3.2 R28.2), USB (Q13.2 R22.1)
VSYS: Power (J16.2 R1.2 TP3.1), MCU_Power (Q3.3 R29.2)
FLASH_PWR_nEN: MCU (U4.E2), Flash (Q7.G R72.2 TP31.1)
LIN.CS: MCU (U4.E7), LIN (R86.2 TP25.1)
LIN.DATA_IN: MCU (U4.D2), LIN (R67.2 TP29.1)
LIN.DATA_OUT: MCU (U4.E3), LIN (R65.2 TP28.1)
LIN.nIS_PWRD: MCU (U4.J4), LIN (Q6.3 R69.2 TP30.1)
MCU_SPI_FLASH.CIPO: MCU (U4.G2), Flash (R80.1 TP39.1)
MCU_SPI_FLASH.COPI: MCU (U4.G1), Flash (R81.1 TP40.1)
MCU_SPI_FLASH.nCS: MCU (U4.H1), Flash (R82.2 TP41.1)
MCU_SPI_FLASH.SCK: MCU (U4.H2), Flash (R79.1 TP38.1)
SENSE.DOORF: MCU (U4.J3), Sensors (R68.1 TP35.1)
SENSE.DOORV: MCU (U4.H8), Sensors (R66.1 TP36.1)
SENSE.PWRF_nEN: MCU (U4.B8), Sensors (Q5.G R56.2 R57.2)
SENSE.PWRV_nEN: MCU (U4.A2), Sensors (Q4.G R47.2 R48.2)
SENSE.VBAT_MEAS: MCU (R117.2), Power (C16.2 R16.2 R18.1 TP7.1)
SENSE.VBAT_MEAS_EN: MCU (U4.H5), Power (Q2.2 Q10.2 R17.1)
TEMPA_I2C.SCL: MCU (R60.2 R97.2), Sensors (R91.2 R94.1 TP37.1)
TEMPA_I2C.SDA: MCU (R51.2 R73.2), Sensors (R92.2 R93.1 TP24.1)
TEMPF_I2C.SCL: MCU (U4.H3), Sensors (R23.2 R89.1 TP17.1)
TEMPF_I2C.SDA: MCU (U4.G3), Sensors (R24.2 R88.1 TP15.1)
TEMPV_I2C.SCL: MCU (U4.B7), Sensors (7 pins)
TEMPV_I2C.SDA: MCU (U4.A7), Sensors (6 pins)
USB.D_N: MCU (U4.D1), USB (R8.1)
USB.D_P: MCU (U4.C1), USB (R9.1)
USB.DETECT: MCU (U4.A6), USB (R5.1 R7.2)
USB.DISCONN: MCU (U4.E8), USB (Q13.1 R22.2)
USB.nFLT: MCU (TP14.1 U4.J7), USB (U18.11)

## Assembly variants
as built: not fitted C23 D7 D15 J2 J3 J6 J8 J9 J11 J14 J15 J16 J17 JP1 JP2 JP3 JP4 JP6 JP8 JP9 Q2 Q8 Q9 Q11 R2 R4 R26 R42 R48 R52 R55 R57 R58 R60 R73 R74 R106 R118 TP12 U7 U9
future_minimal: not fitted D4 D5 D6 D7 D11 D13 D15 FB14 FB15 FB16 J2 J3 J6 J8 J9 J11 J14 J15 J16 J17 JP1 JP2 JP3 JP4 JP6 JP8 JP9 Q2 Q8 Q9 Q11 R1 R2 R3 R4 R8 R9 R10 R11 R12 R13 R21 R26 R27 R28 R29 R30 R31 R32 R33 R34 R42 R45 R46 R48 R51 R52 R53 R54 R55 R57 R58 R60 R63 R65 R67 R71 R73 R74 R76 R82 R83 R85 R86 R90 R91 R92 R93 R94 R97 R116 R118 S1 S2 S3 TP6 TP12 U7 U9 U17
